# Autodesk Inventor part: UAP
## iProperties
Author: Jan-Steinar
Shininess: 20.0
PropertySet Name: _Private Model Information
Created: 2001-01
Part Number: UAP
Document SubType Name: Modeling
Designer: Jan-Steinar
Control State: 0
Master: False
Checked Out: False
PropertySet Name: Design Tracking Control
Density: 0.0
Volumn: 0.0
Area: 0.0
PropertySet Name: Model Information
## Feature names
1. Extrusion1
